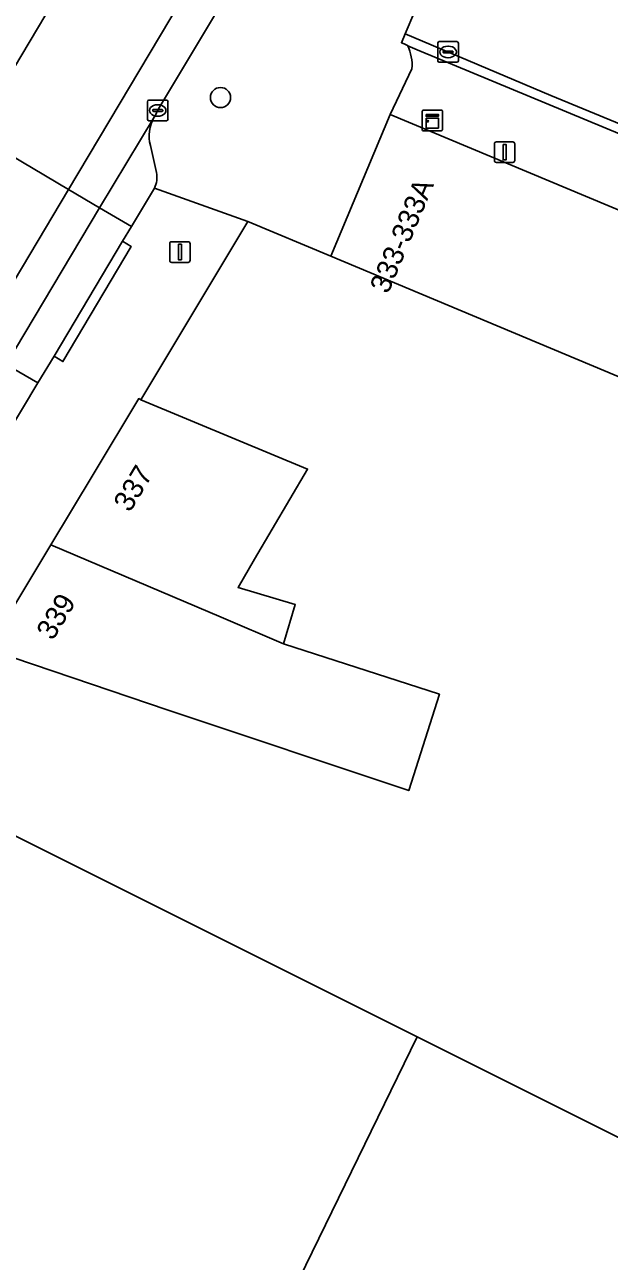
# Model space of a CAD drawing. Extents: x 160554 to 161248, y 385329 to 386506.
# Drawn here: x 160874.9 to 160903.3, y 385796.5 to 385856.5 of the extents above; entities that cross this region are included whole.
import ezdxf

# ---------------------------------------------------------------- set-up
doc = ezdxf.new("R2010")
doc.units = 0
for name, color, linetype in [('IMGEO_Boom', 7, 'Continuous'), ('IMGEO_Erf', 7, 'Continuous'), ('IMGEO_Kast', 7, 'Continuous'), ('IMGEO_Kolk', 7, 'Continuous'), ('IMGEO_Lichtmast', 7, 'Continuous'), ('IMGEO_Pand', 7, 'Continuous'), ('IMGEO_Pand_nummerreeks', 7, 'Continuous'), ('IMGEO_Parkeervlak_gesloten', 7, 'Continuous'), ('IMGEO_Parkeervlak_open', 7, 'Continuous'), ('IMGEO_Rijbaan_lokaal_gesloten', 7, 'Continuous'), ('IMGEO_Rijbaan_lokaal_open', 7, 'Continuous'), ('IMGEO_Voetpad_open', 7, 'Continuous')]:
    doc.layers.add(name, color=color, linetype=linetype)

msp = doc.modelspace()

# ---------------------------------------------------------------- linework, layer by layer
at = {"layer": 'IMGEO_Boom'}
msp.add_circle((160884.412, 385852.947), 0.489, dxfattribs=at)
at = {"layer": 'IMGEO_Erf'}
msp.add_lwpolyline([(160906.809, 385838.126), (160889.773, 385845.251), (160885.744, 385846.936), (160880.552, 385838.277), (160885.17, 385836.358), (160888.636, 385834.918), (160886.057, 385830.556), (160885.263, 385829.176), (160888.04, 385828.348), (160887.47, 385826.436), (160895.037, 385823.997), (160893.546, 385819.32), (160881.83, 385823.242), (160878.148, 385824.485), (160873.41, 385826.084), (160870.819, 385821.842), (160869.463, 385819.623), (160873.936, 385817.389), (160893.966, 385807.383), (160915.948, 385796.401)], dxfattribs=at)
at = {"layer": 'IMGEO_Kast'}
for p, q in [((160894.194, 385851.411), (160894.194, 385852.252)), ((160894.194, 385852.252), (160894.194, 385851.411)), ((160894.269, 385852.336), (160895.11, 385852.336)), ((160895.11, 385852.336), (160894.269, 385852.336)), ((160895.194, 385852.261), (160895.194, 385851.42)), ((160895.194, 385851.42), (160895.194, 385852.261)), ((160895.119, 385851.336), (160894.278, 385851.336)), ((160894.278, 385851.336), (160895.119, 385851.336))]:
    msp.add_line(p, q, dxfattribs=at)
for points in [[(160894.389, 385852.126), (160894.989, 385852.126), (160894.989, 385852.041), (160894.389, 385852.041), (160894.389, 385852.126)], [(160894.389, 385851.951), (160894.989, 385851.951), (160894.989, 385851.462), (160894.389, 385851.462), (160894.389, 385851.951)]]:
    msp.add_lwpolyline(points, dxfattribs=at)
msp.add_circle((160894.473, 385851.8), 0.0377, dxfattribs=at)
for centre, start, end in [((160894.272, 385852.258), 92.4484, 184.28452), ((160894.272, 385852.258), 92.4484, 184.28452), ((160895.116, 385852.258), 2.4484, 94.28452), ((160895.116, 385852.258), 2.4484, 94.28452), ((160894.272, 385851.414), 182.4484, 274.28452), ((160894.272, 385851.414), 182.4484, 274.28452), ((160895.116, 385851.414), 272.4484, 4.28452), ((160895.116, 385851.414), 272.4484, 4.28452)]:
    msp.add_arc(centre, 0.0779, start, end, dxfattribs=at)
at = {"layer": 'IMGEO_Kolk'}
for p, q in [((160895.033, 385855.659), (160895.885, 385855.659)), ((160894.958, 385854.733), (160894.958, 385855.585)), ((160895.217, 385855.153), (160895.217, 385855.165)), ((160895.655, 385855.116), (160895.257, 385855.116)), ((160895.26, 385855.202), (160895.658, 385855.202)), ((160895.446, 385855.439), (160895.471, 385855.439)), ((160895.701, 385855.165), (160895.701, 385855.153)), ((160895.959, 385855.585), (160895.959, 385854.733)), ((160895.885, 385854.659), (160895.033, 385854.659)), ((160895.469, 385854.879), (160895.444, 385854.879)), ((160880.864, 385851.895), (160880.864, 385852.747)), ((160880.939, 385852.821), (160881.791, 385852.821)), ((160881.865, 385852.747), (160881.865, 385851.895)), ((160881.123, 385852.315), (160881.123, 385852.327)), ((160881.561, 385852.278), (160881.163, 385852.278)), ((160881.166, 385852.364), (160881.564, 385852.364)), ((160881.352, 385852.601), (160881.377, 385852.601)), ((160881.607, 385852.327), (160881.607, 385852.315)), ((160881.791, 385851.821), (160880.939, 385851.821)), ((160881.375, 385852.041), (160881.35, 385852.041))]:
    msp.add_line(p, q, dxfattribs=at)
for points in [[(160895.033, 385855.659), (160895.885, 385855.659)], [(160894.958, 385854.733), (160894.958, 385855.585)], [(160895.959, 385855.585), (160895.959, 385854.733)], [(160895.885, 385854.659), (160895.033, 385854.659)], [(160880.864, 385851.895), (160880.864, 385852.747)], [(160880.939, 385852.821), (160881.791, 385852.821)], [(160881.865, 385852.747), (160881.865, 385851.895)], [(160881.791, 385851.821), (160880.939, 385851.821)]]:
    msp.add_lwpolyline(points, dxfattribs=at)
for centre, radius, start, end in [((160895.035, 385855.583), 0.0765, 91.55205, 178.44795), ((160895.035, 385855.583), 0.0765, 91.55205, 178.44795), ((160895.883, 385855.583), 0.0765, 1.55205, 88.44795), ((160895.883, 385855.583), 0.0765, 1.55205, 88.44795), ((160895.257, 385855.162), 0.0403, 85.87752, 175.75265), ((160895.254, 385855.152), 0.0366, 178.93798, 274.71019), ((160895.658, 385855.159), 0.043, 264.86636, 352.45326), ((160895.662, 385855.164), 0.0386, 1.73085, 96.63898), ((160895.035, 385854.735), 0.0765, 181.55205, 268.44795), ((160895.035, 385854.735), 0.0765, 181.55205, 268.44795), ((160895.883, 385854.735), 0.0765, 271.55205, 358.44795), ((160895.883, 385854.735), 0.0765, 271.55205, 358.44795), ((160880.941, 385852.745), 0.0765, 91.55205, 178.44795), ((160880.941, 385852.745), 0.0765, 91.55205, 178.44795), ((160881.789, 385852.745), 0.0765, 1.55205, 88.44795), ((160881.789, 385852.745), 0.0765, 1.55205, 88.44795), ((160881.163, 385852.324), 0.0403, 85.87752, 175.75265), ((160881.16, 385852.314), 0.0366, 178.93798, 274.71019), ((160881.564, 385852.321), 0.043, 264.86636, 352.45326), ((160881.568, 385852.326), 0.0386, 1.73085, 96.63898), ((160880.941, 385851.897), 0.0765, 181.55205, 268.44795), ((160880.941, 385851.897), 0.0765, 181.55205, 268.44795), ((160881.789, 385851.897), 0.0765, 271.55205, 358.44795), ((160881.789, 385851.897), 0.0765, 271.55205, 358.44795)]:
    msp.add_arc(centre, radius, start, end, dxfattribs=at)
for centre, major_axis, ratio, start_param, end_param in [((160895.445, 385855.159), (-0.387, 0.002), 0.722429, 4.712389, 7.853982), ((160895.47, 385855.159), (-0.39, 0.002), 0.717154, 1.570796, 4.712389), ((160881.351, 385852.321), (-0.387, 0.002), 0.722429, 4.712389, 7.853982), ((160881.376, 385852.321), (-0.39, 0.002), 0.717154, 1.570796, 4.712389)]:
    msp.add_ellipse(centre, major_axis=major_axis, ratio=ratio, start_param=start_param, end_param=end_param, dxfattribs=at)
at = {"layer": 'IMGEO_Lichtmast'}
for p, q in [((160897.705, 385849.897), (160897.705, 385850.697)), ((160897.705, 385850.697), (160897.705, 385849.897)), ((160897.805, 385850.797), (160898.595, 385850.797)), ((160898.595, 385850.797), (160897.805, 385850.797)), ((160898.695, 385850.697), (160898.695, 385849.897)), ((160898.695, 385849.897), (160898.695, 385850.697)), ((160898.595, 385849.797), (160897.805, 385849.797)), ((160897.805, 385849.797), (160898.595, 385849.797)), ((160881.948, 385845.052), (160881.948, 385845.852)), ((160881.948, 385845.852), (160881.948, 385845.052)), ((160882.048, 385845.952), (160882.838, 385845.952)), ((160882.838, 385845.952), (160882.048, 385845.952)), ((160882.938, 385845.852), (160882.938, 385845.052)), ((160882.938, 385845.052), (160882.938, 385845.852)), ((160882.838, 385844.952), (160882.048, 385844.952)), ((160882.048, 385844.952), (160882.838, 385844.952))]:
    msp.add_line(p, q, dxfattribs=at)
for points in [[(160898.125, 385850.672), (160898.275, 385850.672), (160898.275, 385849.922), (160898.125, 385849.922), (160898.125, 385850.672)], [(160882.368, 385845.827), (160882.518, 385845.827), (160882.518, 385845.077), (160882.368, 385845.077), (160882.368, 385845.827)]]:
    msp.add_lwpolyline(points, dxfattribs=at)
for centre, start, end in [((160897.805, 385850.697), 90, 180), ((160897.805, 385850.697), 90, 180), ((160898.595, 385850.697), 0, 90), ((160898.595, 385850.697), 360, 90), ((160897.805, 385849.897), 180, 270), ((160897.805, 385849.897), 180, 270), ((160898.595, 385849.897), 270, 0), ((160898.595, 385849.897), 270, 0), ((160882.048, 385845.852), 90, 180), ((160882.048, 385845.852), 90, 180), ((160882.838, 385845.852), 0, 90), ((160882.838, 385845.852), 360, 90), ((160882.048, 385845.052), 180, 270), ((160882.048, 385845.052), 180, 270), ((160882.838, 385845.052), 270, 0), ((160882.838, 385845.052), 270, 0)]:
    msp.add_arc(centre, 0.1, start, end, dxfattribs=at)
at = {"layer": 'IMGEO_Pand'}
for points in [[(160889.773, 385845.251), (160906.809, 385838.126), (160905.918, 385835.995), (160909.497, 385834.498), (160910.376, 385836.599), (160938.63, 385824.783), (160939.592, 385827.082), (160941.467, 385831.564), (160941.521, 385831.694), (160892.651, 385852.132)], [(160888.636, 385834.918), (160885.17, 385836.358), (160880.552, 385838.277), (160880.449, 385838.339), (160878.236, 385834.664), (160876.176, 385831.244), (160884.44, 385827.745), (160887.47, 385826.436), (160888.04, 385828.348), (160885.263, 385829.176), (160886.057, 385830.556)], [(160887.47, 385826.436), (160884.44, 385827.745), (160876.176, 385831.244), (160873.16, 385826.235), (160873.41, 385826.084), (160878.148, 385824.485), (160881.83, 385823.242), (160893.546, 385819.32), (160895.037, 385823.997)], [(160854.26, 385794.183), (160855.238, 385790.712), (160879.963, 385778.684), (160893.966, 385807.383), (160873.936, 385817.389), (160869.463, 385819.623)], [(160901.883, 385768.021), (160904.104, 385772.502), (160915.948, 385796.401), (160893.966, 385807.383), (160879.963, 385778.684)]]:
    msp.add_lwpolyline(points, close=True, dxfattribs=at)
at = {"layer": 'IMGEO_Parkeervlak_gesloten'}
msp.add_lwpolyline([(160851.77, 385799.103), (160866.041, 385823.171), (160869.683, 385829.312), (160875.548, 385839.111), (160874.011, 385840), (160873.793, 385839.628), (160864.955, 385824.786), (160855.849, 385809.517), (160848.677, 385797.449)], dxfattribs=at)
at = {"layer": 'IMGEO_Parkeervlak_open'}
for points in [[(160893.698, 385854.337), (160892.651, 385852.132), (160941.521, 385831.694), (160941.467, 385831.564), (160942.449, 385831.196), (160943.83, 385834.567), (160893.952, 385855.26)], [(160893.952, 385855.26), (160893.513, 385855.461), (160893.484, 385855.474)], [(160881.187, 385851.991), (160878.545, 385847.59), (160880.086, 385846.691), (160881.207, 385848.555)], [(160881.3, 385849.316), (160881.009, 385850.616)]]:
    msp.add_lwpolyline(points, dxfattribs=at)
msp.add_lwpolyline([(160875.548, 385839.111), (160876.333, 385840.395), (160879.65, 385845.972), (160880.086, 385846.691), (160878.545, 385847.59), (160874.011, 385840)], close=True, dxfattribs=at)
for centre, radius, start, end in [((160891.699, 385854.549), 2.01, 353.93573, 27.38268), ((160882.866, 385851.075), 1.913, 151.37351, 193.87414), ((160880.276, 385849.055), 1.056, 331.75613, 14.30901)]:
    msp.add_arc(centre, radius, start, end, dxfattribs=at)
at = {"layer": 'IMGEO_Rijbaan_lokaal_gesloten'}
for points in [[(160906.014, 385896.856), (160897.988, 385883.524), (160891.331, 385872.486), (160877.039, 385848.482), (160878.545, 385847.59), (160881.187, 385851.991), (160881.268, 385852.125), (160881.363, 385852.322), (160884.455, 385857.488), (160890.464, 385867.601), (160892.832, 385871.586), (160899.487, 385882.621), (160907.495, 385895.924), (160908.821, 385897.94)], [(160898.183, 385897.59), (160891.727, 385886.965), (160883.962, 385873.891), (160883.897, 385873.781), (160883.288, 385872.716), (160881.662, 385870.025), (160875.631, 385859.932), (160873.631, 385856.59), (160873.526, 385856.411), (160871.328, 385852.673), (160870.961, 385852.081), (160872.467, 385851.189), (160885.466, 385872.996), (160893.23, 385886.069), (160896.724, 385891.912), (160899.657, 385896.647)], [(160899.657, 385896.647), (160896.724, 385891.912), (160893.23, 385886.069), (160885.466, 385872.996), (160872.467, 385851.189), (160877.039, 385848.482), (160891.331, 385872.486), (160897.988, 385883.524), (160906.014, 385896.856)], [(160936.711, 385845.699), (160929.905, 385848.43), (160929.029, 385848.781), (160927.245, 385849.527), (160924.113, 385850.835), (160916.29, 385854.104), (160912.588, 385855.659), (160903.848, 385859.395), (160899.484, 385861.26), (160896.184, 385862.656), (160893.378, 385856.039), (160900.444, 385853.054), (160936.154, 385838.328), (160943.719, 385835.176), (160953.399, 385831.56)]]:
    msp.add_lwpolyline(points, dxfattribs=at)
msp.add_lwpolyline([(160872.512, 385840.903), (160874.011, 385840), (160878.545, 385847.59), (160877.039, 385848.482)], close=True, dxfattribs=at)
at = {"layer": 'IMGEO_Rijbaan_lokaal_open'}
msp.add_lwpolyline([(160953.399, 385831.56), (160943.719, 385835.176), (160936.154, 385838.328), (160900.444, 385853.054), (160893.378, 385856.039), (160893.195, 385855.607), (160893.326, 385855.547), (160893.484, 385855.474), (160893.513, 385855.461), (160893.952, 385855.26), (160943.83, 385834.567), (160947.696, 385833.124), (160950.55, 385832.059), (160954.657, 385830.526), (160962.252, 385827.866), (160967.092, 385826.298), (161022.331, 385808.398)], dxfattribs=at)
msp.add_lwpolyline([(160872.467, 385851.189), (160868.007, 385843.619), (160872.512, 385840.903), (160877.039, 385848.482)], close=True, dxfattribs=at)
at = {"layer": 'IMGEO_Voetpad_open'}
for points in [[(160892.832, 385871.586), (160890.464, 385867.601), (160890.893, 385867.346), (160884.884, 385857.233), (160884.455, 385857.488), (160881.363, 385852.322), (160881.268, 385852.125), (160881.187, 385851.991)], [(160893.484, 385855.474), (160893.326, 385855.547), (160893.195, 385855.607), (160893.378, 385856.039), (160896.184, 385862.656), (160899.484, 385861.26), (160903.848, 385859.395)], [(160881.207, 385848.555), (160885.744, 385846.936), (160889.773, 385845.251), (160892.651, 385852.132), (160893.698, 385854.337)], [(160881.009, 385850.616), (160881.3, 385849.316)], [(160869.463, 385819.623), (160870.819, 385821.842), (160873.41, 385826.084), (160873.16, 385826.235), (160876.176, 385831.244), (160878.236, 385834.664), (160880.449, 385838.339), (160880.552, 385838.277), (160885.744, 385846.936), (160881.207, 385848.555), (160880.086, 385846.691), (160879.65, 385845.972), (160880.079, 385845.717), (160876.762, 385840.14), (160876.333, 385840.395), (160875.548, 385839.111), (160869.683, 385829.312), (160870.113, 385829.057), (160866.471, 385822.916), (160866.041, 385823.171), (160851.77, 385799.103)]]:
    msp.add_lwpolyline(points, dxfattribs=at)
msp.add_lwpolyline([(160876.333, 385840.395), (160876.762, 385840.14), (160880.079, 385845.717), (160879.65, 385845.972)], close=True, dxfattribs=at)
for centre, radius, start, end in [((160891.699, 385854.549), 2.01, 353.93573, 27.38268), ((160882.866, 385851.075), 1.913, 151.37351, 193.87414), ((160880.276, 385849.055), 1.056, 331.75613, 14.30901)]:
    msp.add_arc(centre, radius, start, end, dxfattribs=at)

# ---------------------------------------------------------------- texts
at = {"layer": 'IMGEO_Pand_nummerreeks'}
for s, rotation, p in [('333-333A', 67.30273, (160892.547, 385843.383)), ('337', 58.74536, (160880.015, 385832.781)), ('339', 58.9459, (160876.275, 385826.562))]:
    msp.add_text(s, height=1, rotation=rotation, dxfattribs=at).set_placement(p)

doc.saveas('drawing.dxf')
